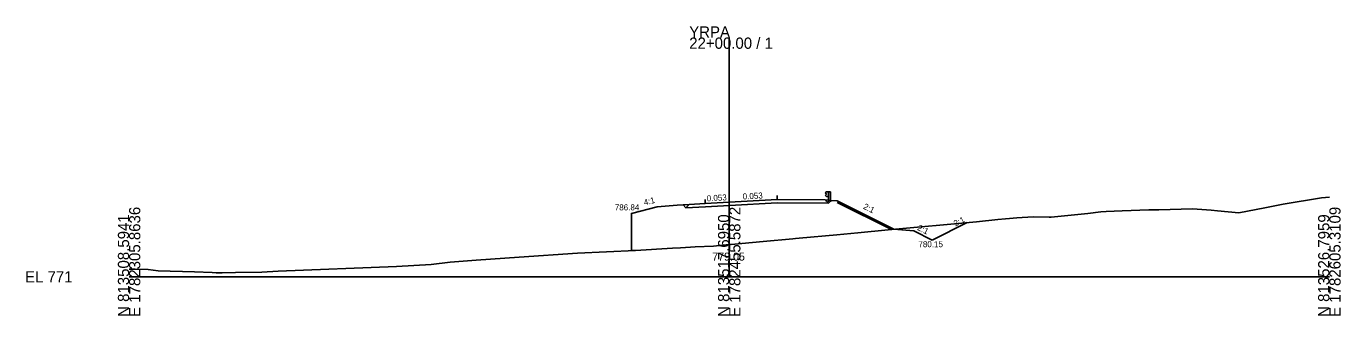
# Model space of a CAD drawing. Extents: x -26 to 2603, y -14 to 9545.
# Drawn here: x 974.3 to 1302.8, y 1990.3 to 2062.5 of the extents above; entities that cross this region are included whole.
import ezdxf

# ---------------------------------------------------------------- set-up
doc = ezdxf.new("R2010")
doc.units = 0
for name, color, linetype in [('Exist Cross Section Cell', 7, 'Continuous'), ('Exist XS Center Line Elevation Label', 7, 'Continuous'), ('Exist XS Ground Line', 7, 'Continuous'), ('Prop XS DDE', 7, 'Continuous'), ('Prop XS Ditch Standard Text', 7, 'Continuous'), ('Prop XS Dump Level', 7, 'Continuous'), ('Prop XS Earthwork Shape', 7, 'Continuous'), ('Prop XS EOT Tick Mark', 7, 'Continuous'), ('Prop XS Finish Grade', 7, 'Continuous'), ('Prop XS Finish Grade Earthwork', 7, 'Continuous'), ('Prop XS Finish Grade Paved Shoulder', 7, 'Continuous'), ('Prop XS Finish Grade Pavement', 7, 'Continuous'), ('Prop XS Guardrail', 7, 'Continuous'), ('Prop XS Hydro Fill Slope Data', 7, 'Continuous'), ('Prop XS Pvmt Edge Slope', 7, 'Continuous'), ('Prop XS SE Text', 7, 'Continuous'), ('Prop XS Side Slope Text', 7, 'Continuous'), ('Prop XS Subgrade Earthwork', 7, 'Continuous')]:
    doc.layers.add(name, color=color, linetype=linetype)

msp = doc.modelspace()

# ---------------------------------------------------------------- linework, layer by layer
at = {"layer": 'Exist Cross Section Cell'}
for p, q in [((1150, 2000), (1150, 2059.72)), ((1000, 2000), (1150, 2000)), ((1150, 2000), (1300, 2000))]:
    msp.add_line(p, q, dxfattribs=at)
at = {"layer": 'Exist XS Ground Line'}
for p, q in [((1277.4, 2015.96), (1283.86, 2017.25)), ((1283.86, 2017.25), (1285.09, 2017.51)), ((1285.09, 2017.51), (1288.43, 2018.12)), ((1288.43, 2018.12), (1298.07, 2019.74)), ((1298.07, 2019.74), (1300, 2019.91)), ((1211.81, 2013.74), (1217.16, 2014.31)), ((1217.16, 2014.31), (1219.02, 2014.49)), ((1219.02, 2014.49), (1220.08, 2014.57)), ((1220.08, 2014.57), (1221.88, 2014.69)), ((1221.88, 2014.69), (1225.96, 2014.96)), ((1225.96, 2014.96), (1229.97, 2014.88)), ((1229.97, 2014.88), (1230.47, 2014.88)), ((1230.47, 2014.88), (1239.63, 2015.84)), ((1239.63, 2015.84), (1242.87, 2016.22)), ((1242.87, 2016.22), (1244.18, 2016.28)), ((1244.18, 2016.28), (1248.25, 2016.44)), ((1248.25, 2016.44), (1254.87, 2016.7)), ((1254.87, 2016.7), (1257.35, 2016.75)), ((1257.35, 2016.75), (1265.82, 2016.94)), ((1265.82, 2016.94), (1270.49, 2016.62)), ((1270.49, 2016.62), (1272.07, 2016.49)), ((1272.07, 2016.49), (1277.4, 2015.96)), ((1176.86, 2010.49), (1180.4, 2010.83)), ((1180.4, 2010.83), (1182.16, 2011.01)), ((1182.16, 2011.01), (1189.72, 2011.73)), ((1189.72, 2011.73), (1211.81, 2013.74)), ((1137.86, 2007.27), (1140.33, 2007.4)), ((1140.33, 2007.4), (1141.52, 2007.46)), ((1141.52, 2007.46), (1146.05, 2007.69)), ((1146.05, 2007.69), (1150, 2008.05)), ((1150, 2008.05), (1150.46, 2008.09)), ((1150.46, 2008.09), (1158.47, 2008.82)), ((1158.47, 2008.82), (1165.92, 2009.52)), ((1165.92, 2009.52), (1166.59, 2009.59)), ((1166.59, 2009.59), (1167.49, 2009.66)), ((1167.49, 2009.66), (1176.86, 2010.49)), ((1080.22, 2003.67), (1086.72, 2004.14)), ((1086.72, 2004.14), (1097.51, 2004.9)), ((1097.51, 2004.9), (1112.06, 2005.92)), ((1112.06, 2005.92), (1126.59, 2006.59)), ((1126.59, 2006.59), (1135.86, 2007.19)), ((1135.86, 2007.19), (1137.86, 2007.27)), ((1000, 2001.9), (1001.54, 2001.9)), ((1001.54, 2001.9), (1004.76, 2001.79)), ((1004.76, 2001.79), (1007.25, 2001.49)), ((1007.25, 2001.49), (1016.37, 2001.26)), ((1016.37, 2001.26), (1020.79, 2001.05)), ((1020.79, 2001.05), (1021.75, 2001.03)), ((1021.75, 2001.03), (1023.27, 2001.03)), ((1023.27, 2001.03), (1026.62, 2001.06)), ((1026.62, 2001.06), (1033.22, 2001.18)), ((1033.22, 2001.18), (1037.3, 2001.39)), ((1037.3, 2001.39), (1066.87, 2002.61)), ((1066.87, 2002.61), (1075.52, 2003.07)), ((1075.52, 2003.07), (1080.22, 2003.67))]:
    msp.add_line(p, q, dxfattribs=at)
at = {"layer": 'Prop XS DDE'}
for p, q in [((1191.16, 2011.86), (1196.16, 2011.44)), ((1196.16, 2011.44), (1200.74, 2009.15)), ((1200.74, 2009.15), (1209.51, 2013.53))]:
    msp.add_line(p, q, dxfattribs=at)
at = {"layer": 'Prop XS Dump Level'}
for p, q in [((1144, 2018.3), (1150, 2018.62)), ((1150, 2018.62), (1162, 2019.26))]:
    msp.add_line(p, q, dxfattribs=at)
at = {"layer": 'Prop XS Earthwork Shape'}
msp.add_lwpolyline([(1125.57, 2006.55), (1126.59, 2006.59), (1135.86, 2007.19), (1137.86, 2007.27), (1140.33, 2007.4), (1141.52, 2007.46), (1146.05, 2007.69), (1150, 2008.05), (1150.46, 2008.09), (1158.47, 2008.82), (1165.92, 2009.52), (1166.59, 2009.59), (1167.49, 2009.66), (1176.86, 2010.49), (1180.4, 2010.83), (1182.16, 2011.01), (1189.72, 2011.73), (1191.16, 2011.86), (1177, 2018.94), (1175.48, 2019.06), (1174.8, 2018.39), (1162.02, 2018.47), (1150.04, 2017.83), (1144.04, 2017.51), (1139.16, 2017.25), (1138.45, 2017.97), (1137, 2017.85), (1132, 2017.45), (1125.57, 2015.84)], close=True, dxfattribs=at)
at = {"layer": 'Prop XS EOT Tick Mark'}
for p, q in [((1144, 2018.3), (1144, 2019.3)), ((1162, 2019.26), (1162, 2020.26))]:
    msp.add_line(p, q, dxfattribs=at)
at = {"layer": 'Prop XS Finish Grade'}
for p, q in [((1140, 2018.09), (1138.45, 2017.97)), ((1174, 2019.18), (1175.48, 2019.06))]:
    msp.add_line(p, q, dxfattribs=at)
at = {"layer": 'Prop XS Finish Grade Earthwork'}
for p, q in [((1132, 2017.45), (1125.57, 2015.84)), ((1137, 2017.85), (1132, 2017.45)), ((1137, 2017.85), (1138.45, 2017.97)), ((1175.48, 2019.06), (1177, 2018.94)), ((1177, 2018.94), (1191.16, 2011.86)), ((1125.57, 2015.84), (1125.57, 2006.56))]:
    msp.add_line(p, q, dxfattribs=at)
at = {"layer": 'Prop XS Finish Grade Paved Shoulder'}
for p, q in [((1144, 2018.3), (1140, 2018.09)), ((1162, 2019.26), (1174, 2019.18))]:
    msp.add_line(p, q, dxfattribs=at)
at = {"layer": 'Prop XS Finish Grade Pavement'}
for p, q in [((1144, 2018.3), (1150, 2018.62)), ((1150, 2018.62), (1162, 2019.26))]:
    msp.add_line(p, q, dxfattribs=at)
at = {"layer": 'Prop XS Guardrail'}
for p, q in [((1174.03, 2021.01), (1174, 2020.95)), ((1174, 2020.95), (1174.03, 2020.89)), ((1174.32, 2021.21), (1174.03, 2021.01)), ((1174.03, 2020.89), (1174.32, 2020.69)), ((1174.32, 2020.6), (1174.03, 2020.4)), ((1174.82, 2021.21), (1174.32, 2021.21)), ((1174.32, 2020.69), (1174.32, 2020.6)), ((1175.32, 2021.21), (1174.82, 2021.21)), ((1174.82, 2021.21), (1174.82, 2018.71)), ((1175.32, 2018.71), (1175.32, 2021.21)), ((1174.03, 2020.4), (1174, 2020.34)), ((1174, 2020.34), (1174.03, 2020.28)), ((1174.03, 2020.28), (1174.32, 2020.08)), ((1174.32, 2020.08), (1174.82, 2020.08))]:
    msp.add_line(p, q, dxfattribs=at)
at = {"layer": 'Prop XS Hydro Fill Slope Data'}
for p, q in [((1132, 2017.45), (1125.57, 2015.84)), ((1177, 2018.58), (1190.54, 2011.8))]:
    msp.add_line(p, q, dxfattribs=at)
at = {"layer": 'Prop XS Pvmt Edge Slope'}
for p, q in [((1140, 2018.09), (1139.16, 2017.25)), ((1174, 2019.18), (1174.8, 2018.39))]:
    msp.add_line(p, q, dxfattribs=at)
at = {"layer": 'Prop XS Subgrade Earthwork'}
for p, q in [((1139.16, 2017.25), (1138.45, 2017.97)), ((1144.04, 2017.51), (1139.16, 2017.25)), ((1144.04, 2017.51), (1150.04, 2017.83)), ((1150.04, 2017.83), (1162.02, 2018.47)), ((1162.02, 2018.47), (1174.8, 2018.39)), ((1174.8, 2018.39), (1175.48, 2019.06))]:
    msp.add_line(p, q, dxfattribs=at)

# ---------------------------------------------------------------- texts
at = {"layer": 'Exist Cross Section Cell'}
for s, p in [('YRPA', (1140, 2059.72)), ('22+00.00 / 1', (1140, 2056.92)), ('EL 771', (974, 1998.6))]:
    msp.add_text(s, height=2.8, dxfattribs=at).set_placement(p)
for s, p in [('E 1782305.8636', (1002.8, 1990)), ('E 1782455.5872', (1152.8, 1990)), ('E 1782605.3109', (1302.8, 1990)), ('N 813508.5941', (1000, 1990)), ('N 813517.6950', (1150, 1990)), ('N 813526.7959', (1300, 1990))]:
    msp.add_text(s, height=2.8, rotation=90, dxfattribs=at).set_placement(p)
at = {"layer": 'Exist XS Center Line Elevation Label'}
msp.add_text('779.05', height=2, dxfattribs=at).set_placement((1145.74, 2004.05))
at = {"layer": 'Prop XS Ditch Standard Text'}
for s, p in [('786.84', (1121.4, 2016.59)), ('780.15', (1197.29, 2007.4))]:
    msp.add_text(s, height=1.5, dxfattribs=at).set_placement(p)
at = {"layer": 'Prop XS Dump Level'}
for p in [(1132, 2017.41), (1174, 2018.78)]:
    msp.add_text('Case4', height=0.04, dxfattribs=at).set_placement(p)
at = {"layer": 'Prop XS SE Text'}
for p in [(1144.41, 2018.83), (1153.41, 2019.31)]:
    msp.add_text('0.053', height=1.5, rotation=3.0505, dxfattribs=at).set_placement(p)
at = {"layer": 'Prop XS Side Slope Text'}
for s, rotation, p in [('4:1', 14.0362, (1128.84, 2017.8)), ('2:1', 333.4349, (1183.36, 2017.07)), ('2:1', 26.5651, (1206.56, 2012.53)), ('2:1', 333.4349, (1196.87, 2011.78))]:
    msp.add_text(s, height=1.5, rotation=rotation, dxfattribs=at).set_placement(p)

doc.saveas('drawing.dxf')
